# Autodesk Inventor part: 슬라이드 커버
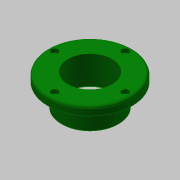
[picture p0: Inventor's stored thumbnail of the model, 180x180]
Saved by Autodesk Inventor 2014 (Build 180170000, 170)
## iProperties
Created: 2015-10
Part Number: 슬라이드 커버
Document SubType Name: Modeling
Designer: mdu
Density: 2.71 g/cm^3
Material: 알루미늄 6061
Mass: 221.924 g
Surface Area: 243.242 cm^2
Volume: 81.8907 cm^3
Appearance: 진녹색
Author: mdu
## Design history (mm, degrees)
sketch "스케치1"
  geometry: C1 r 47.5 at (0, 0); C2 r 32.5 at (0, 0); 1 further point
  constraints: 2 centre point, 2 coincident
  dimensions: "d33" = 95 diameter of C1; "d35" = 65 diameter of C2
extrude "돌출1" new body sketch "스케치1" distance "d0" = 10; taper "d1" = 0 deg
extrude "돌출2" join sketch "스케치1" distance "d2" = 26; taper "d3" = 0 deg
hole "구멍1" diameter "d6" = 50; stored, may be unused: countersink angle "d10" = 90 deg, drill point angle "d12" = 118 deg; dims "d4" = 10, "d5" = 10, "d7" = 6, "d8" = 4, "d9" = 2, "d11" = 8
sketch "스케치2" dims "d36" = 80
  geometry: 4 further points
  constraints: 2 coincident, 2 vertical alignment, 2 other
hole "구멍2" sketch "스케치2" at (0, 40) diameter "d13" = 4.5; stored, may be unused: countersink angle "d17" = 90 deg, drill point angle "d19" = 118 deg; dims "d14" = 6, "d15" = 8, "d16" = 4.4, "d18" = 8
fillet "모깎기1" dims "d23" = 3
chamfer "모따기1" distance "d24" = 1; stored, may be unused: second distance "d25" = 2, angle "d26" = 45 deg
sketch "스케치3"
  geometry: C1 r 25 at (0, 0); C2 r 30 at (0, 0); C3 r 26 at (0, 0) reference; 1 further point
  constraints: 2 centre point, 2 coincident
  dimensions: "d27" = 60 diameter of C2
extrude "돌출3" cut sketch "스케치3" distance "d28" = 3; taper "d29" = 0 deg
chamfer "모따기2" distance "d30" = 1; stored, may be unused: second distance "d31" = 2, angle "d32" = 45 deg
node "솔리드1"
pattern_circular "원형 패턴1" dims angle "d21" = 360 deg
